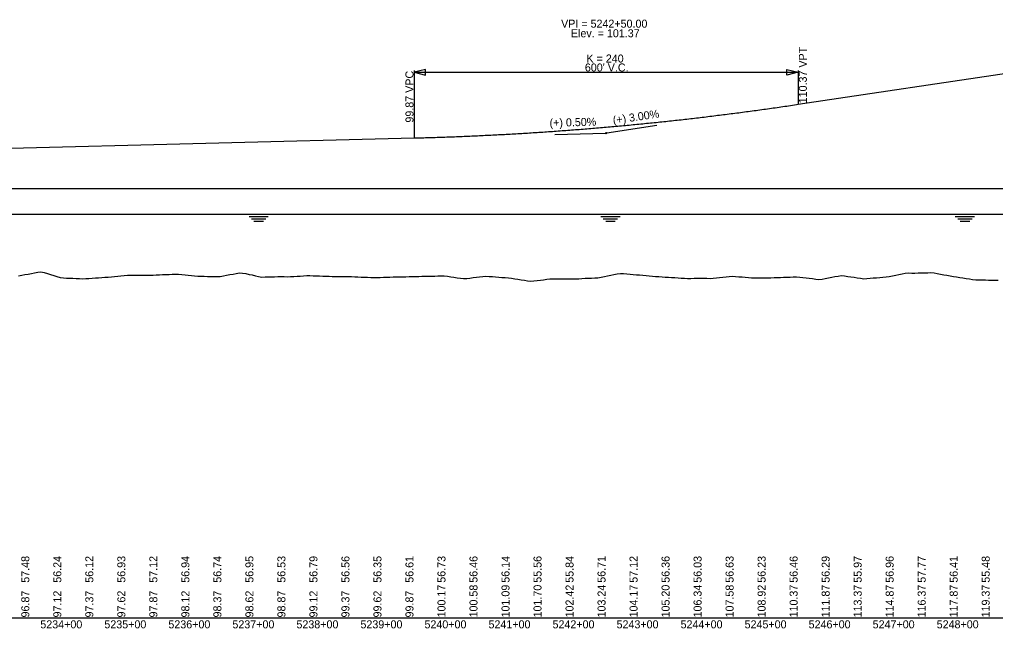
# Model space of a CAD drawing. Extents: x 2147288 to 2220488, y 740833 to 759333.
# Drawn here: x 2155715 to 2157239, y 750067 to 751018 of the extents above; entities that cross this region are included whole.
import ezdxf

# ---------------------------------------------------------------- set-up
doc = ezdxf.new("R2010")
doc.units = 0
for name, color, linetype in [('RD_DDB_GradeTX', 7, 'Continuous'), ('RD_DDB_Profile_Elev', 7, 'Continuous'), ('RD_DDB_Profile_EX', 7, 'Continuous'), ('RD_DDB_Profile_Lbl', 7, 'Continuous'), ('RD_DDB_Profile_PR', 7, 'Continuous'), ('RD_DDB_StaTX', 7, 'Continuous'), ('RD_DDB_StripGrade', 7, 'Continuous'), ('RD_DDB_VCLbl', 7, 'Continuous'), ('RD_GPK_Profile_Cell', 7, 'Continuous')]:
    doc.layers.add(name, color=color, linetype=linetype)

msp = doc.modelspace()

# ---------------------------------------------------------------- linework, layer by layer
at = {"layer": 'RD_DDB_GradeTX'}
for p, q in [((2156710.2, 750852.1), (2156632.1, 750840.4)), ((2156551.1, 750838.3), (2156630.1, 750840.2))]:
    msp.add_line(p, q, dxfattribs=at)
msp.add_circle((2156631.1, 750840.3), 1, dxfattribs=at)
at = {"layer": 'RD_DDB_Profile_Elev'}
for p, q in [((2154716.7, 750754), (2158451.2, 750754)), ((2154763.1, 750714), (2159128.1, 750714)), ((2156073.4, 750710.3), (2156103.4, 750710.3)), ((2156077.1, 750706.5), (2156099.6, 750706.5)), ((2156080.9, 750702.8), (2156095.9, 750702.8)), ((2156622.8, 750710.3), (2156652.8, 750710.3)), ((2156626.5, 750706.5), (2156649, 750706.5)), ((2156630.3, 750702.8), (2156645.3, 750702.8)), ((2157176.4, 750710.3), (2157206.4, 750710.3)), ((2157180.2, 750706.5), (2157202.7, 750706.5)), ((2157183.9, 750702.8), (2157198.9, 750702.8))]:
    msp.add_line(p, q, dxfattribs=at)
at = {"layer": 'RD_DDB_Profile_EX'}
for points in [[(2155713.3, 750617.7), (2155718.3, 750618.5), (2155723.3, 750619.4), (2155728.3, 750620.3), (2155733.3, 750621.2), (2155738.3, 750622.1), (2155743.3, 750623.1), (2155748.3, 750623.8), (2155753.3, 750622.5), (2155758.3, 750621), (2155763.3, 750619.5), (2155768.3, 750618), (2155773.3, 750616.5), (2155778.3, 750615.1), (2155783.3, 750614.3), (2155788.3, 750614), (2155793.3, 750613.8), (2155798.3, 750613.6), (2155803.3, 750613.4), (2155808.3, 750613.1), (2155813.3, 750612.9), (2155818.3, 750613.1), (2155823.3, 750613.4), (2155828.3, 750613.8), (2155833.3, 750614.2), (2155838.3, 750614.6), (2155843.3, 750615), (2155848.3, 750615.4), (2155853.3, 750615.6), (2155858.3, 750616), (2155863.3, 750616.5), (2155868.3, 750616.9), (2155873.3, 750617.4), (2155878.3, 750617.8), (2155883.3, 750618.3), (2155888.3, 750618.4), (2155893.3, 750618.5), (2155898.3, 750618.5), (2155903.3, 750618.6), (2155908.3, 750618.6), (2155913.3, 750618.6), (2155918.3, 750618.7), (2155923.3, 750618.6), (2155928.3, 750618.9), (2155933.3, 750619.1), (2155938.3, 750619.4), (2155943.3, 750619.6), (2155948.3, 750619.8), (2155953.3, 750620.1), (2155958.3, 750620.3), (2155963.3, 750619.9), (2155968.3, 750619.4), (2155973.3, 750618.9), (2155978.3, 750618.4), (2155983.3, 750617.9), (2155988.3, 750617.4), (2155993.3, 750617.2), (2155998.3, 750617), (2156003.3, 750616.9), (2156008.3, 750616.7), (2156013.3, 750616.6), (2156018.3, 750616.4), (2156023.3, 750616.3), (2156028.3, 750616.6), (2156033.3, 750617.6), (2156038.3, 750618.5)], [(2157038.3, 750613.3), (2157043.3, 750613.8), (2157048.3, 750614.2), (2157053.3, 750614.6), (2157058.3, 750615.1), (2157063.3, 750615.5), (2157068.3, 750615.9), (2157073.3, 750616.7), (2157078.3, 750617.7), (2157083.3, 750618.7), (2157088.3, 750619.7), (2157093.3, 750620.7), (2157098.3, 750621.7), (2157103.3, 750622), (2157108.3, 750621.8), (2157113.3, 750621.9), (2157118.3, 750622), (2157123.3, 750622.1), (2157128.3, 750622.2), (2157133.3, 750622.3), (2157138.3, 750622.8), (2157143.3, 750622.1), (2157148.3, 750621.1), (2157153.3, 750620.2), (2157158.3, 750619.2), (2157163.3, 750618.3), (2157168.3, 750617.3), (2157173.3, 750616.7), (2157178.3, 750615.9), (2157183.3, 750615.1), (2157188.3, 750614.3), (2157193.3, 750613.5), (2157198.3, 750612.7), (2157203.3, 750611.9), (2157208.3, 750611.3), (2157213.3, 750611.2), (2157218.3, 750611.1), (2157223.3, 750611), (2157228.3, 750610.9), (2157233.3, 750610.8), (2157238.3, 750610.7), (2157243.3, 750610.6)], [(2156038.3, 750618.5), (2156043.3, 750619.4), (2156048.3, 750620.3), (2156053.3, 750621.2), (2156058.3, 750622.1), (2156063.3, 750621.9), (2156068.3, 750620.9), (2156073.3, 750619.8), (2156078.3, 750618.8), (2156083.3, 750617.7), (2156088.3, 750616.7), (2156093.3, 750615.6), (2156098.3, 750615.9), (2156103.3, 750616), (2156108.3, 750616.1), (2156113.3, 750616.1), (2156118.3, 750616.2), (2156123.3, 750616.3), (2156128.3, 750616.3), (2156133.3, 750615.9), (2156138.3, 750616.2), (2156143.3, 750616.6), (2156148.3, 750616.9), (2156153.3, 750617.2), (2156158.3, 750617.6), (2156163.3, 750617.9), (2156168.3, 750617.9), (2156173.3, 750617.7), (2156178.3, 750617.5), (2156183.3, 750617.3), (2156188.3, 750617.1), (2156193.3, 750616.9), (2156198.3, 750616.8), (2156203.3, 750616.7), (2156208.3, 750616.6), (2156213.3, 750616.6), (2156218.3, 750616.5), (2156223.3, 750616.4), (2156228.3, 750616.3), (2156233.3, 750616.2), (2156238.3, 750616), (2156243.3, 750615.8), (2156248.3, 750615.6), (2156253.3, 750615.4), (2156258.3, 750615.2), (2156263.3, 750614.9), (2156268.3, 750614.8), (2156273.3, 750615), (2156278.3, 750615.1), (2156283.3, 750615.3), (2156288.3, 750615.4), (2156293.3, 750615.6), (2156298.3, 750615.7), (2156303.3, 750615.7), (2156308.3, 750615.7), (2156313.3, 750615.8), (2156318.3, 750616), (2156323.3, 750616.2), (2156328.3, 750616.4), (2156333.3, 750616.5), (2156338.3, 750616.7), (2156343.3, 750616.8), (2156348.3, 750616.9), (2156353.3, 750617), (2156358.3, 750617.1), (2156363.3, 750617.2), (2156368.3, 750617.3), (2156373.3, 750617.6), (2156378.3, 750617.5), (2156383.3, 750616.8), (2156388.3, 750616.1), (2156393.3, 750615.3), (2156398.3, 750614.6), (2156403.3, 750613.9), (2156408.3, 750613.2), (2156413.3, 750613.3), (2156418.3, 750614), (2156423.3, 750614.7), (2156428.3, 750615.4), (2156433.3, 750616.1), (2156438.3, 750616.7), (2156443.3, 750617), (2156448.3, 750616.6), (2156453.3, 750616.2), (2156458.3, 750615.8), (2156463.3, 750615.4), (2156468.3, 750615.1), (2156473.3, 750614.7), (2156478.3, 750614.4), (2156483.3, 750613.9), (2156488.3, 750613), (2156493.3, 750612.2), (2156498.3, 750611.3), (2156503.3, 750610.5), (2156508.3, 750609.6), (2156513.3, 750609.1), (2156518.3, 750609.6), (2156523.3, 750610.3), (2156528.3, 750610.9), (2156533.3, 750611.5), (2156538.3, 750612.1)], [(2156538.3, 750612.1), (2156543.3, 750612.7), (2156548.3, 750613), (2156553.3, 750612.8), (2156558.3, 750612.8), (2156563.3, 750612.7), (2156568.3, 750612.7), (2156573.3, 750612.6), (2156578.3, 750612.6), (2156583.3, 750612.7), (2156588.3, 750613), (2156593.3, 750613.3), (2156598.3, 750613.6), (2156603.3, 750613.8), (2156608.3, 750614.1), (2156613.3, 750614.4), (2156618.3, 750614.6), (2156623.3, 750615.4), (2156628.3, 750616.4), (2156633.3, 750617.4), (2156638.3, 750618.5), (2156643.3, 750619.5), (2156648.3, 750620.5), (2156653.3, 750621.3), (2156658.3, 750621), (2156663.3, 750620.6), (2156668.3, 750620.1), (2156673.3, 750619.7), (2156678.3, 750619.3), (2156683.3, 750618.8), (2156688.3, 750618.4), (2156693.3, 750617.9), (2156698.3, 750617.5), (2156703.3, 750617.1), (2156708.3, 750616.6), (2156713.3, 750616.2), (2156718.3, 750615.8), (2156723.3, 750615.6), (2156728.3, 750615.4), (2156733.3, 750615.1), (2156738.3, 750614.8), (2156743.3, 750614.4), (2156748.3, 750614.1), (2156753.3, 750613.7), (2156758.3, 750613.5), (2156763.3, 750613.5), (2156768.3, 750613.6), (2156773.3, 750613.6), (2156778.3, 750613.6), (2156783.3, 750613.6), (2156788.3, 750613.6), (2156793.3, 750613.5), (2156798.3, 750613.9), (2156803.3, 750614.4), (2156808.3, 750614.9), (2156813.3, 750615.4), (2156818.3, 750615.9), (2156823.3, 750616.5), (2156828.3, 750616.8), (2156833.3, 750616.5), (2156838.3, 750616.1), (2156843.3, 750615.7), (2156848.3, 750615.4), (2156853.3, 750615), (2156858.3, 750614.6), (2156863.3, 750614.4), (2156868.3, 750614.5), (2156873.3, 750614.5), (2156878.3, 750614.6), (2156883.3, 750614.6), (2156888.3, 750614.6), (2156893.3, 750614.7), (2156898.3, 750614.8), (2156903.3, 750615), (2156908.3, 750615.2), (2156913.3, 750615.4), (2156918.3, 750615.5), (2156923.3, 750615.7), (2156928.3, 750615.9), (2156933.3, 750615.6), (2156938.3, 750614.9), (2156943.3, 750614.3), (2156948.3, 750613.7), (2156953.3, 750613.1), (2156958.3, 750612.4), (2156963.3, 750611.8), (2156968.3, 750612.4), (2156973.3, 750613.4), (2156978.3, 750614.3), (2156983.3, 750615.3), (2156988.3, 750616.2), (2156993.3, 750617.2), (2156998.3, 750618.1), (2157003.3, 750617.5), (2157008.3, 750616.7), (2157013.3, 750615.9), (2157018.3, 750615.2), (2157023.3, 750614.4), (2157028.3, 750613.6), (2157033.3, 750613), (2157038.3, 750613.3)]]:
    msp.add_lwpolyline(points, dxfattribs=at)
at = {"layer": 'RD_DDB_Profile_PR'}
for p, q in [((2156931.1, 750885.3), (2157281.1, 750937.8)), ((2154731.1, 750792.8), (2156331.1, 750832.8))]:
    msp.add_line(p, q, dxfattribs=at)
msp.add_spline([(2156331.1, 750832.8), (2156343.1, 750833.1), (2156355.1, 750833.4), (2156367.1, 750833.8), (2156379.1, 750834.2), (2156391.1, 750834.6), (2156403.1, 750835.1), (2156415.1, 750835.6), (2156427.1, 750836.1), (2156439.1, 750836.7), (2156451.1, 750837.3), (2156463.1, 750837.9), (2156475.1, 750838.5), (2156487.1, 750839.2), (2156499.1, 750839.9), (2156511.1, 750840.6), (2156523.1, 750841.4), (2156535.1, 750842.2), (2156547.1, 750843), (2156559.1, 750843.9), (2156571.1, 750844.8), (2156583.1, 750845.7), (2156595.1, 750846.6), (2156607.1, 750847.6), (2156619.1, 750848.6), (2156631.1, 750849.6), (2156643.1, 750850.7), (2156655.1, 750851.8), (2156667.1, 750852.9), (2156679.1, 750854.1), (2156691.1, 750855.3), (2156703.1, 750856.5), (2156715.1, 750857.7), (2156727.1, 750859), (2156739.1, 750860.3), (2156751.1, 750861.6), (2156763.1, 750863), (2156775.1, 750864.4), (2156787.1, 750865.8), (2156799.1, 750867.3), (2156811.1, 750868.8), (2156823.1, 750870.3), (2156835.1, 750871.8), (2156847.1, 750873.4), (2156859.1, 750875), (2156871.1, 750876.6), (2156883.1, 750878.3), (2156895.1, 750880), (2156907.1, 750881.7), (2156919.1, 750883.5), (2156931.1, 750885.3)], degree=3, dxfattribs=at)
at = {"layer": 'RD_DDB_VCLbl'}
for p, q in [((2156331.1, 750937.8), (2156331.1, 750832.8)), ((2156331.1, 750935.3), (2156931.1, 750935.3)), ((2156931.1, 750937.8), (2156931.1, 750885.3))]:
    msp.add_line(p, q, dxfattribs=at)
for points in [[(2156349.1, 750939.8), (2156331.1, 750935.3), (2156349.1, 750930.8)], [(2156913.1, 750939.8), (2156931.1, 750935.3), (2156913.1, 750930.8)]]:
    msp.add_lwpolyline(points, close=True, dxfattribs=at)
at = {"layer": 'RD_GPK_Profile_Cell'}
msp.add_line((2148888.3, 750083.4), (2170488.3, 750083.4), dxfattribs=at)

# ---------------------------------------------------------------- texts
at = {"layer": 'RD_DDB_GradeTX'}
for s, rotation, p in [('(+) 3.00%', 8.5308, (2156642.4, 750854)), ('(+) 0.50%', 1.4321, (2156542.8, 750850.1))]:
    msp.add_text(s, height=12.5, rotation=rotation, dxfattribs=at).set_placement(p)
at = {"layer": 'RD_DDB_Profile_Lbl'}
for s, p in [('VPI = 5242+50.00', (2156560.7, 751004.9)), ('Elev. = 101.37', (2156576, 750989.9))]:
    msp.add_text(s, height=12.5, dxfattribs=at).set_placement(p)
at = {"layer": 'RD_DDB_StaTX'}
for s, p in [('5234+00', (2155747.3, 750067.2)), ('5235+00', (2155847.3, 750067.2)), ('5236+00', (2155947.3, 750067.2)), ('5237+00', (2156047.3, 750067.2)), ('5238+00', (2156147.3, 750067.2)), ('5239+00', (2156247.3, 750067.2)), ('5240+00', (2156347.3, 750067.2)), ('5241+00', (2156447.3, 750067.2)), ('5242+00', (2156547.3, 750067.2)), ('5243+00', (2156647.3, 750067.2)), ('5244+00', (2156747.3, 750067.2)), ('5245+00', (2156847.3, 750067.2)), ('5246+00', (2156947.3, 750067.2)), ('5247+00', (2157047.3, 750067.2)), ('5248+00', (2157147.3, 750067.2))]:
    msp.add_text(s, height=12.5, dxfattribs=at).set_placement(p)
at = {"layer": 'RD_DDB_StripGrade'}
for s, p in [('110.37 VPT', (2156944.5, 750886.8)), ('99.87 VPC', (2156330.1, 750856.7)), ('57.48', (2155730.1, 750138.4)), ('56.24', (2155780.1, 750138.4)), ('56.12', (2155830.1, 750138.4)), ('56.93', (2155880.1, 750138.4)), ('57.12', (2155930.1, 750138.4)), ('56.94', (2155980.1, 750138.4)), ('56.74', (2156030.1, 750138.4)), ('56.95', (2156080.1, 750138.4)), ('56.53', (2156130.1, 750138.4)), ('56.79', (2156180.1, 750138.4)), ('56.56', (2156230.1, 750138.4)), ('56.35', (2156280.1, 750138.4)), ('56.61', (2156330.1, 750138.4)), ('56.73', (2156380.1, 750138.4)), ('56.46', (2156430.1, 750138.4)), ('56.14', (2156480.1, 750138.4)), ('55.56', (2156530.1, 750138.4)), ('55.84', (2156580.1, 750138.4)), ('56.71', (2156630.1, 750138.4)), ('57.12', (2156680.1, 750138.4)), ('56.36', (2156730.1, 750138.4)), ('56.03', (2156780.1, 750138.4)), ('56.63', (2156830.1, 750138.4)), ('56.23', (2156880.1, 750138.4)), ('56.46', (2156930.1, 750138.4)), ('56.29', (2156980.1, 750138.4)), ('55.97', (2157030.1, 750138.4)), ('56.96', (2157080.1, 750138.4)), ('57.77', (2157130.1, 750138.4)), ('56.41', (2157180.1, 750138.4)), ('55.48', (2157230.1, 750138.4)), ('103.24', (2156630.1, 750084.2)), ('106.34', (2156780.1, 750084.2)), ('96.87', (2155730.1, 750084.2)), ('97.12', (2155780.1, 750084.2)), ('97.37', (2155830.1, 750084.2)), ('97.62', (2155880.1, 750084.2)), ('97.87', (2155930.1, 750084.2)), ('98.12', (2155980.1, 750084.2)), ('98.37', (2156030.1, 750084.2)), ('98.62', (2156080.1, 750084.2)), ('98.87', (2156130.1, 750084.2)), ('99.12', (2156180.1, 750084.2)), ('99.37', (2156230.1, 750084.2)), ('99.62', (2156280.1, 750084.2)), ('99.87', (2156330.1, 750084.2)), ('100.17', (2156380.1, 750084.2)), ('100.58', (2156430.1, 750084.2)), ('101.09', (2156480.1, 750084.2)), ('101.70', (2156530.1, 750084.2)), ('102.42', (2156580.1, 750084.2)), ('104.17', (2156680.1, 750084.2)), ('105.20', (2156730.1, 750084.2)), ('107.58', (2156830.1, 750084.2)), ('108.92', (2156880.1, 750084.2)), ('110.37', (2156930.1, 750084.2)), ('111.87', (2156980.1, 750084.2)), ('113.37', (2157030.1, 750084.2)), ('114.87', (2157080.1, 750084.2)), ('116.37', (2157130.1, 750084.2)), ('117.87', (2157180.1, 750084.2)), ('119.37', (2157230.1, 750084.2))]:
    msp.add_text(s, height=12.5, rotation=90, dxfattribs=at).set_placement(p)
at = {"layer": 'RD_DDB_VCLbl'}
for s, p in [('K = 240', (2156600.3, 750950.5)), ("600' V.C.", (2156597.8, 750936.5))]:
    msp.add_text(s, height=12.5, dxfattribs=at).set_placement(p)

doc.saveas('drawing.dxf')
